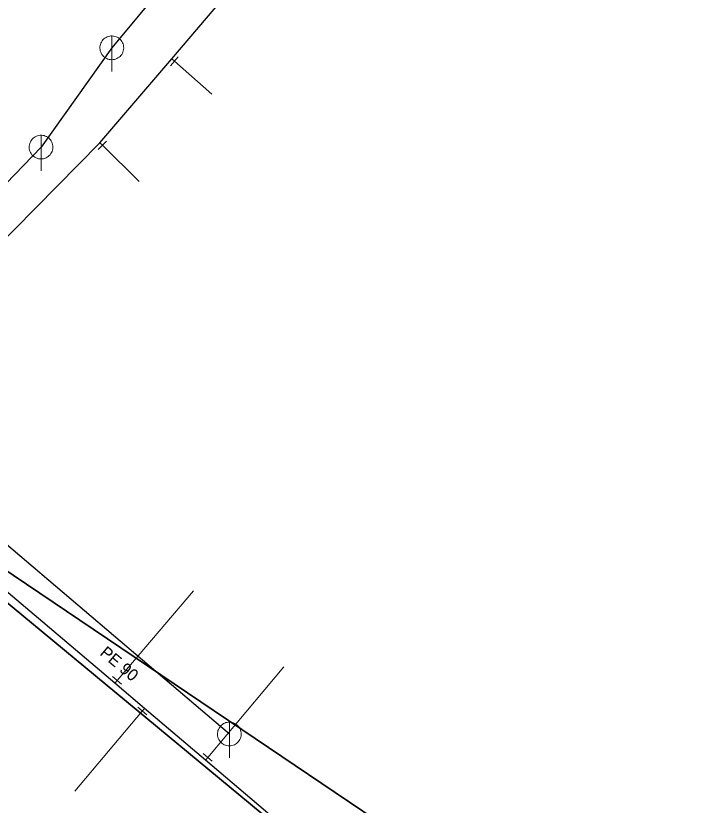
# Model space of a CAD drawing. Extents: x -779496 to -779026, y -977086 to -976624.
# Drawn here: x -779259.7 to -779202.2, y -976922.6 to -976856.2 of the extents above; entities that cross this region are included whole.
import ezdxf

# ---------------------------------------------------------------- set-up
doc = ezdxf.new("R2010")
doc.units = 0
doc.header["$LTSCALE"] = 0.4
doc.linetypes.add('MEDIUM_DASHED', pattern=[4.5, 3, -1.5])
for name, color, linetype, lineweight in [('1', 7, 'MEDIUM_DASHED', 25), ('13', 7, 'Continuous', 13), ('14', 7, 'Continuous', 13), ('17', 7, 'Continuous', 25), ('22', 7, 'Continuous', 13), ('34', 7, 'Continuous', 13)]:
    doc.layers.add(name, color=color, linetype=linetype, lineweight=lineweight)

msp = doc.modelspace()

# ---------------------------------------------------------------- linework, layer by layer
at = {"layer": '13'}
for p, q in [((-779243.221, -976862.741), (-779246.376, -976859.977)), ((-779249.338, -976870.109), (-779252.44, -976867.052)), ((-779244.778, -976904.556), (-779251.204, -976912.109)), ((-779237.157, -976910.969), (-779243.57, -976918.588)), ((-779254.77, -976921.426), (-779249.085, -976914.694))]:
    msp.add_line(p, q, dxfattribs=at)
at = {"layer": '14'}
for p, q in [((-779246.603, -976859.784), (-779246.376, -976859.977)), ((-779252.653, -976866.844), (-779252.44, -976867.052)), ((-779251.398, -976912.338), (-779251.204, -976912.109)), ((-779248.891, -976914.465), (-779249.085, -976914.694)), ((-779243.764, -976918.817), (-779243.57, -976918.588))]:
    msp.add_line(p, q, dxfattribs=at)
at = {"layer": '14', "lineweight": 25}
msp.add_line((-779241.75, -976916.623), (-779276.684, -976886.967), dxfattribs=at)
for points in [[(-779187.41, -976790.809), (-779190.807, -976793.919), (-779200.812, -976803.077), (-779239.083, -976843.704), (-779240.711, -976845.665), (-779251.651, -976858.85), (-779257.611, -976867.208)], [(-779257.611, -976867.208), (-779265.041, -976874.906), (-779276.684, -976886.967)]]:
    msp.add_lwpolyline(points, dxfattribs=at)
at = {"layer": '17'}
for points in [[(-779276.545, -976891.073), (-779272.473, -976886.943), (-779252.653, -976866.844), (-779246.603, -976859.784), (-779242.228, -976854.603), (-779234.164, -976845.175), (-779227.585, -976837.452), (-779212.579, -976818.883), (-779210.76, -976816.627), (-779191.487, -976792.772), (-779191.372, -976792.629), (-779190.682, -976791.787), (-779189.552, -976790.451), (-779187.15, -976792.396)], [(-779226.798, -976933.215), (-779233.45, -976927.57), (-779243.764, -976918.817), (-779248.891, -976914.465), (-779251.398, -976912.338), (-779255.068, -976909.223), (-779276.159, -976891.399)]]:
    msp.add_lwpolyline(points, dxfattribs=at)
at = {"layer": '17', "lineweight": 35}
for points in [[(-779294.52, -976873.809), (-779286.179, -976884.319), (-779226.903, -976933.326), (-779213.28, -976944.579), (-779208.355, -976950.874)], [(-779283.847, -976885.578), (-779269.588, -976896.763), (-779267.93, -976897.881), (-779206.76, -976939.131), (-779203.521, -976944.031)]]:
    msp.add_lwpolyline(points, dxfattribs=at)
at = {"layer": '22'}
for p, q in [((-779251.651, -976860.85), (-779251.65, -976857.85)), ((-779257.611, -976869.208), (-779257.61, -976866.208)), ((-779241.75, -976918.623), (-779241.749, -976915.623))]:
    msp.add_line(p, q, dxfattribs=at)
for points in [[(-779250.651, -976858.85), (-779250.656, -976858.741), (-779250.674, -976858.633), (-779250.704, -976858.527), (-779250.744, -976858.426), (-779250.796, -976858.329), (-779250.858, -976858.239), (-779250.93, -976858.156), (-779251.01, -976858.082), (-779251.098, -976858.016), (-779251.192, -976857.961), (-779251.292, -976857.916), (-779251.397, -976857.883), (-779251.504, -976857.861), (-779251.613, -976857.851), (-779251.723, -976857.853), (-779251.831, -976857.867), (-779251.938, -976857.892), (-779252.041, -976857.929), (-779252.139, -976857.978), (-779252.231, -976858.036), (-779252.317, -976858.105), (-779252.394, -976858.182), (-779252.463, -976858.268), (-779252.522, -976858.36), (-779252.57, -976858.458), (-779252.607, -976858.561), (-779252.633, -976858.668), (-779252.647, -976858.776), (-779252.65, -976858.886), (-779252.64, -976858.995), (-779252.619, -976859.102), (-779252.585, -976859.206), (-779252.541, -976859.306), (-779252.486, -976859.401), (-779252.42, -976859.489), (-779252.346, -976859.569), (-779252.263, -976859.641), (-779252.173, -976859.703), (-779252.077, -976859.755), (-779251.975, -976859.796), (-779251.87, -976859.826), (-779251.762, -976859.844), (-779251.652, -976859.85), (-779251.543, -976859.844), (-779251.435, -976859.826), (-779251.33, -976859.797), (-779251.228, -976859.756), (-779251.131, -976859.704), (-779251.041, -976859.642), (-779250.958, -976859.571), (-779250.883, -976859.491), (-779250.818, -976859.403), (-779250.762, -976859.309), (-779250.718, -976859.209), (-779250.684, -976859.105), (-779250.662, -976858.997), (-779250.652, -976858.888)], [(-779256.611, -976867.208), (-779256.616, -976867.099), (-779256.634, -976866.991), (-779256.664, -976866.885), (-779256.704, -976866.784), (-779256.756, -976866.687), (-779256.818, -976866.597), (-779256.89, -976866.514), (-779256.97, -976866.44), (-779257.058, -976866.374), (-779257.152, -976866.319), (-779257.252, -976866.274), (-779257.357, -976866.241), (-779257.464, -976866.219), (-779257.573, -976866.209), (-779257.683, -976866.211), (-779257.791, -976866.225), (-779257.898, -976866.25), (-779258.001, -976866.287), (-779258.099, -976866.336), (-779258.191, -976866.394), (-779258.277, -976866.463), (-779258.354, -976866.54), (-779258.423, -976866.626), (-779258.482, -976866.718), (-779258.53, -976866.816), (-779258.567, -976866.919), (-779258.593, -976867.026), (-779258.607, -976867.134), (-779258.61, -976867.244), (-779258.6, -976867.353), (-779258.579, -976867.46), (-779258.545, -976867.564), (-779258.501, -976867.664), (-779258.446, -976867.759), (-779258.38, -976867.847), (-779258.306, -976867.927), (-779258.223, -976867.999), (-779258.133, -976868.061), (-779258.037, -976868.113), (-779257.935, -976868.154), (-779257.83, -976868.184), (-779257.722, -976868.202), (-779257.612, -976868.208), (-779257.503, -976868.202), (-779257.395, -976868.184), (-779257.29, -976868.155), (-779257.188, -976868.114), (-779257.091, -976868.062), (-779257.001, -976868), (-779256.918, -976867.929), (-779256.843, -976867.849), (-779256.778, -976867.761), (-779256.722, -976867.667), (-779256.678, -976867.567), (-779256.644, -976867.463), (-779256.622, -976867.355), (-779256.612, -976867.246)], [(-779240.75, -976916.623), (-779240.755, -976916.514), (-779240.773, -976916.406), (-779240.803, -976916.3), (-779240.843, -976916.199), (-779240.895, -976916.102), (-779240.957, -976916.012), (-779241.029, -976915.929), (-779241.109, -976915.855), (-779241.197, -976915.789), (-779241.291, -976915.734), (-779241.391, -976915.689), (-779241.496, -976915.656), (-779241.603, -976915.634), (-779241.712, -976915.624), (-779241.822, -976915.626), (-779241.93, -976915.64), (-779242.037, -976915.665), (-779242.14, -976915.702), (-779242.238, -976915.751), (-779242.33, -976915.809), (-779242.416, -976915.878), (-779242.493, -976915.955), (-779242.562, -976916.041), (-779242.621, -976916.133), (-779242.669, -976916.231), (-779242.706, -976916.334), (-779242.732, -976916.441), (-779242.746, -976916.549), (-779242.749, -976916.659), (-779242.739, -976916.768), (-779242.718, -976916.875), (-779242.684, -976916.979), (-779242.64, -976917.079), (-779242.585, -976917.174), (-779242.519, -976917.262), (-779242.445, -976917.342), (-779242.362, -976917.414), (-779242.272, -976917.476), (-779242.176, -976917.528), (-779242.074, -976917.569), (-779241.969, -976917.599), (-779241.861, -976917.617), (-779241.751, -976917.623), (-779241.642, -976917.617), (-779241.534, -976917.599), (-779241.429, -976917.57), (-779241.327, -976917.529), (-779241.23, -976917.477), (-779241.14, -976917.415), (-779241.057, -976917.344), (-779240.982, -976917.264), (-779240.917, -976917.176), (-779240.861, -976917.082), (-779240.817, -976916.982), (-779240.783, -976916.878), (-779240.761, -976916.77), (-779240.751, -976916.661)]]:
    msp.add_lwpolyline(points, close=True, dxfattribs=at)
at = {"layer": '34'}
for p, q in [((-779246.051, -976859.596), (-779246.701, -976860.356)), ((-779252.089, -976866.695), (-779252.791, -976867.407)), ((-779251.585, -976911.785), (-779250.823, -976912.432)), ((-779248.703, -976915.017), (-779249.465, -976914.37)), ((-779243.951, -976918.264), (-779243.189, -976918.911))]:
    msp.add_line(p, q, dxfattribs=at)

# ---------------------------------------------------------------- texts
at = {"layer": '1'}
msp.add_text('PE 90 ', height=1, rotation=320, dxfattribs=at).set_placement((-779252.727, -976909.914))

doc.saveas('drawing.dxf')
